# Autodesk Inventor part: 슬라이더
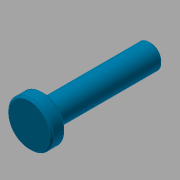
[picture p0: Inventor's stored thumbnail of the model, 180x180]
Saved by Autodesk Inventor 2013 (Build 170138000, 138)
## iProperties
Created: 2019-01
Part Number: 슬라이더
Material: 강철, 연강
Document SubType Name: Modeling
Designer: mduedu
Density: 1 g/cm^3
Author: mduedu
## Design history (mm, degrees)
sketch "스케치1"
  geometry: L1 (0, 0)-(8, 0); L2 (8, 0)-(8, 13); L3 (8, 13)-(0, 13); L4 (0, 13)-(0, 0); L5 (8, 0)-(70, 0); L6 (70, 0)-(70, 7); L7 (70, 7)-(8, 7); L8 (8, 7)-(8, 0)
  constraints: 16 end point, 4 parallel, 2 horizontal, 2 perpendicular
  dimensions: "d0" = 70 distance between parallel lines of L6 L4; "d2" = 8 distance of L2.end L3.end; "d3" = 26 diameter of L3 L1; "d4" = 14 diameter of L7 L5
revolve "회전1" sketch "스케치1" stored, may be unused: angle "d5" = 90 deg
chamfer "모따기1" distance "d6" = 1; stored, may be unused: second distance "d7" = 2, angle "d8" = 45 deg
hole "구멍1" diameter "d14" = 4.134; stored, may be unused: countersink angle "d18" = 60 deg, drill point angle "d20" = 118 deg; dims "d15" = 12, "d16" = 6.3, "d17" = 2, "d19" = 15, "d26" = 10, "d27" = 10
chamfer "모따기4" distance "d24" = 1; stored, may be unused: second distance "d25" = 2, angle "d28" = 30 deg
sketch "스케치2"
  geometry: L1 (70, 2.067)-(70, -2.067) reference; L2 (70, 0)-(68, 0); L3 (68, 0)-(68, 2.067); L4 (70, 3.222)-(70, 0); L5 (70, 3.222)-(68, 2.067); L6 (55, 2.067)-(70, 2.067) reference; 1 further point
  constraints: 8 end point, 1 horizontal, 1 midpoint, 1 parallel, 1 perpendicular, 1 point on line
  dimensions: "d29" = 2 horizontal distance of L4.start L3.end; "d31" = 30 deg angle of L2 L5
revolve "회전2" sketch "스케치2" stored, may be unused: angle "d33" = 90 deg
node "솔리드1"
